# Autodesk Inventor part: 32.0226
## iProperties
Created: 2012-10
Part Number: 32.0226
Document SubType Name: Modeling
Designer: Administrator
Density: 7.85 g/cm^3
Material: Steel
Mass: 66.6128 g
Surface Area: 45.9878 cm^2
Volume: 8.48571 cm^3
Description: LIMIT STOP FOR CABLE TROLLEY
Stock Number: 32.0226 LIMIT STOP FOR CABLE TROLLEY
Translation Standard: STEP AP214IS
FileName: 32_0226_0_3.stp
PreProcessor: ACIS
PostProcessor: Build: 236a, Release: 2009 RTM - Date: Fri 02/22/2008
Sent Units: MM
Uncertainty: 1e-06
Author: Administrator
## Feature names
1. Base1
